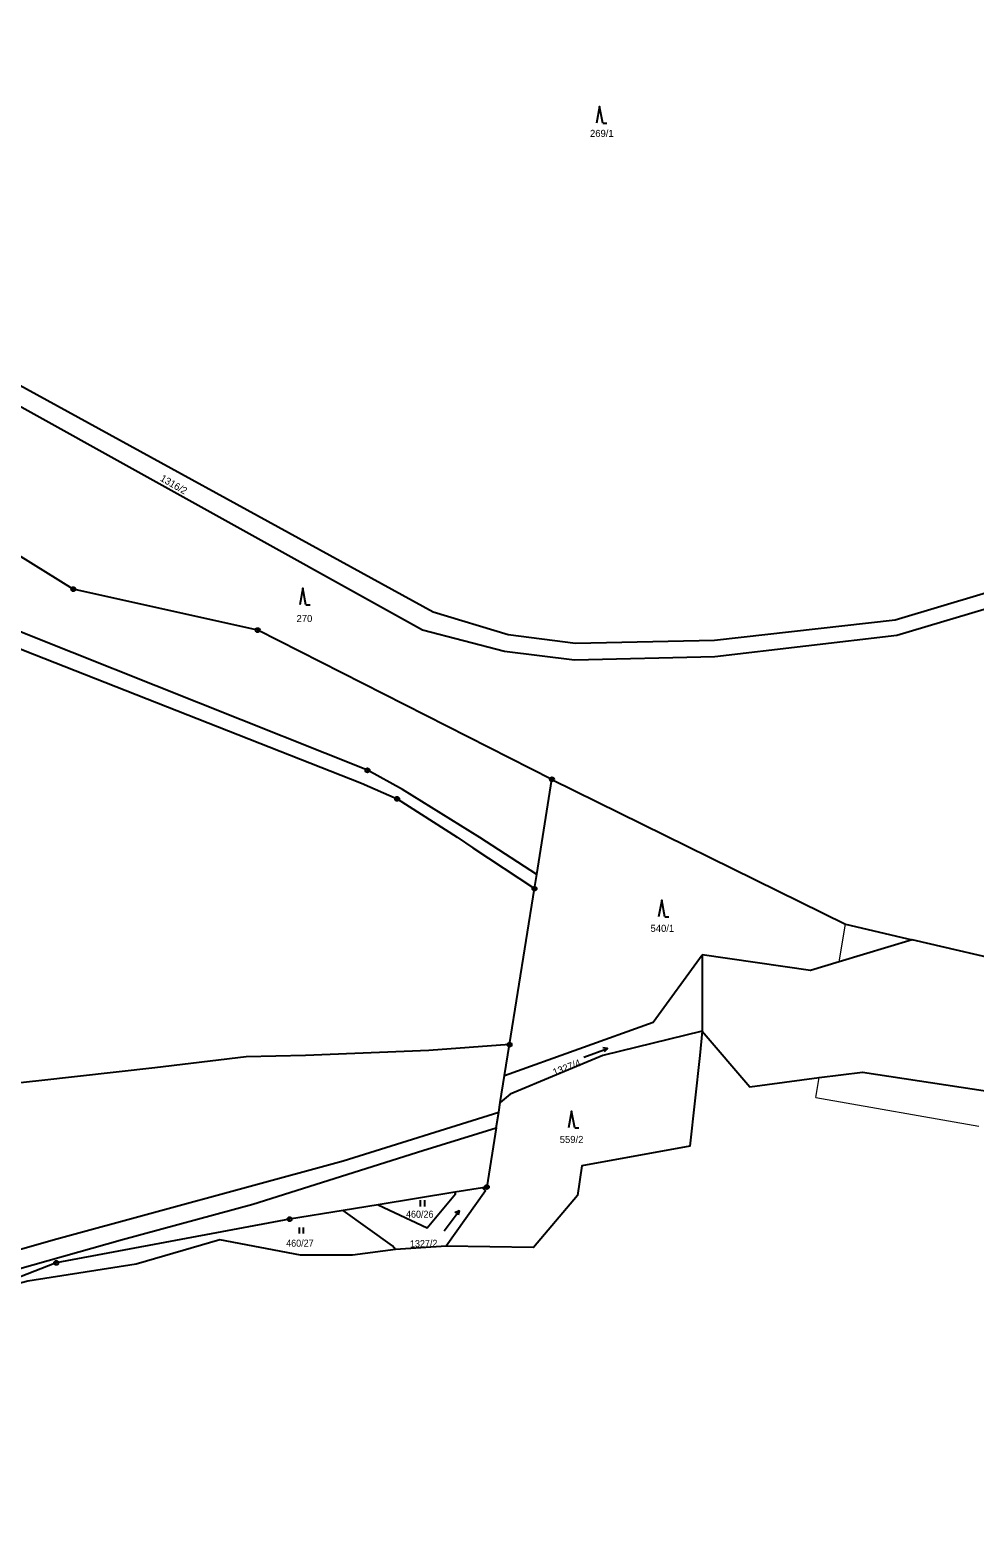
# Model space of a CAD drawing. Extents: x -872229 to -869198, y -1075981 to -1074329.
# Drawn here: x -869771.9 to -869544.8, y -1075316.1 to -1074953.6 of the extents above; entities that cross this region are included whole.
import ezdxf

# ---------------------------------------------------------------- set-up
doc = ezdxf.new("R2010")
doc.units = 0
doc.header["$LTSCALE"] = 0.68
for name, color, linetype, lineweight in [('1', 7, 'Continuous', 25), ('3', 7, 'Continuous', 25), ('4', 7, 'Continuous', 13), ('8', 7, 'Continuous', 25)]:
    doc.layers.add(name, color=color, linetype=linetype, lineweight=lineweight)
doc.layers.add('2', color=7, linetype='Continuous')

msp = doc.modelspace()

# ---------------------------------------------------------------- linework, layer by layer
at = {"layer": '1'}
for p, q in [((-869650.14, -1075156.59), (-869646.48, -1075133.71)), ((-869650.68, -1075159.97), (-869650.14, -1075156.59)), ((-869656.67, -1075197.48), (-869650.68, -1075159.97)), ((-869610.34, -1075175.92), (-869610.41, -1075194.26)), ((-869659.87, -1075217.53), (-869659.27, -1075213.75)), ((-869659.27, -1075213.75), (-869658.9, -1075211.43)), ((-869663.18, -1075231.88), (-869669.81, -1075232.97)), ((-869669.81, -1075232.97), (-869688.29, -1075235.98)), ((-869688.29, -1075235.98), (-869696.7, -1075237.35))]:
    msp.add_line(p, q, dxfattribs=at)
for points in [[(-869650.14, -1075156.59), (-869663.85, -1075147.72), (-869682.43, -1075136.12), (-869690.84, -1075131.53), (-869772.1, -1075099.13), (-869844.86, -1075069.32), (-869848.3, -1075067.94), (-869907.96, -1075043.15), (-869940.96, -1075028.98), (-869973.59, -1075015.13), (-869995.78, -1075005.14), (-870001.42, -1074998.91), (-870003.58, -1074990.56), (-870002.58, -1074982.27), (-870000.39, -1074972.48), (-869996.55, -1074953.58)], [(-869646.48, -1075133.71), (-869717.21, -1075097.82), (-869761.54, -1075087.98), (-869810.64, -1075057.49), (-869851.57, -1075052.75), (-869911.59, -1075031.3), (-869976.94, -1074996.08), (-869983.15, -1074985.9), (-869984.78, -1074967.82), (-869973.47, -1074958.19)], [(-869479.66, -1075070.06), (-869480.79, -1075070.33), (-869510.31, -1075083.29), (-869563.58, -1075099.14), (-869607.33, -1075104.27), (-869641.09, -1075105.05), (-869657.9, -1075102.95), (-869677.61, -1075097.87), (-869787.66, -1075036.73), (-869804.59, -1075028.78), (-869863.04, -1075007.07), (-869931.86, -1074972.77), (-869958.29, -1074958.82), (-869973.47, -1074958.19)], [(-869929.31, -1074968.38), (-869861.33, -1075003.43), (-869802.73, -1075024.51), (-869785.27, -1075033.02), (-869675.06, -1075093.42), (-869657.01, -1075098.88), (-869640.84, -1075100.95), (-869607.45, -1075100.23), (-869563.99, -1075095.38), (-869511.48, -1075079.68), (-869481.91, -1075066.7), (-869467.98, -1075063.1), (-869463.59, -1075063.5)], [(-870007.09, -1074982.34), (-870007.65, -1074991.46), (-870005.25, -1074999.97), (-870000.07, -1075005.82), (-869979.18, -1075015.56), (-869947.14, -1075029.34), (-869914.15, -1075043.78), (-869849.68, -1075071.21), (-869846.22, -1075072.58), (-869773.51, -1075102.64), (-869692.27, -1075134.64), (-869683.71, -1075138.39), (-869669.29, -1075147.62), (-869665.53, -1075150.2), (-869650.68, -1075159.97)], [(-869646.48, -1075133.71), (-869575.93, -1075168.51), (-869559.89, -1075172.26)], [(-869460.16, -1075167.77), (-869533.72, -1075178.38), (-869559.89, -1075172.26), (-869577.48, -1075177.56)], [(-869657.86, -1075204.9), (-869622.14, -1075192.1), (-869610.34, -1075175.92)], [(-869577.48, -1075177.56), (-869584.37, -1075179.64), (-869610.34, -1075175.92)], [(-869656.67, -1075197.48), (-869676.11, -1075198.92), (-869705.7, -1075200.11), (-869719.96, -1075200.44), (-869741.96, -1075203.08), (-869769.79, -1075206.17), (-869793.73, -1075208.74), (-869802.97, -1075209.8), (-869816.06, -1075208.55), (-869855.81, -1075204.07), (-869887.65, -1075202.22), (-869902.63, -1075201.56), (-869926.76, -1075200.04), (-869936.33, -1075199.65), (-869949.18, -1075200.24), (-869974.1, -1075201.42), (-869979.65, -1075201.82), (-869989.18, -1075200.96), (-870032.43, -1075196.35), (-870040.36, -1075195.42)], [(-869610.41, -1075194.26), (-869610.95, -1075200.13), (-869613.36, -1075221.91), (-869639.34, -1075226.59), (-869640.32, -1075233.75), (-869650.96, -1075246.23), (-869671.93, -1075245.96), (-869684.1, -1075246.72)], [(-869610.41, -1075194.26), (-869634.23, -1075200.13), (-869656.49, -1075209.41), (-869658.9, -1075211.43)], [(-869610.41, -1075194.26), (-869598.91, -1075207.6), (-869582.25, -1075205.43), (-869571.84, -1075204.08), (-869531.81, -1075210.17)], [(-869658.9, -1075211.43), (-869657.86, -1075204.9), (-869656.67, -1075197.48)], [(-870385.12, -1075316.07), (-870355.23, -1075301.89), (-870314.21, -1075282.93), (-870280.58, -1075266.36), (-870265.86, -1075261.9), (-870249.15, -1075258.69), (-870230, -1075254.57), (-870219.5, -1075254.87), (-870207.6, -1075253.65), (-870190, -1075251.81), (-870178.96, -1075255.5), (-870167.23, -1075255.17), (-870141.46, -1075254.46), (-870092.41, -1075254.3), (-870019.81, -1075254.06), (-869952.16, -1075254.08), (-869902.23, -1075254.21), (-869809.43, -1075253.56), (-869784.98, -1075249.67), (-869765.49, -1075244.15), (-869696.7, -1075225.43), (-869659.27, -1075213.75)], [(-870086.74, -1075257.68), (-870033.35, -1075257.7), (-869997.08, -1075257.38), (-869953.96, -1075258.61), (-869925.38, -1075258.43), (-869886.31, -1075258.63), (-869811.48, -1075257.76), (-869785.54, -1075254.45), (-869749.68, -1075244.36), (-869718.38, -1075235.81), (-869677.56, -1075222.96), (-869659.87, -1075217.53)], [(-869659.87, -1075217.53), (-869662.14, -1075231.71), (-869663.18, -1075231.88)], [(-869663.18, -1075231.88), (-869662.47, -1075232.67), (-869671.93, -1075245.96)], [(-869688.29, -1075235.98), (-869676.45, -1075241.57), (-869669.7, -1075233.33), (-869669.81, -1075232.97)], [(-869709.56, -1075239.45), (-869765.65, -1075249.96), (-869788.46, -1075258.83)], [(-869684.1, -1075246.72), (-869684.85, -1075245.87), (-869696.7, -1075237.35), (-869709.56, -1075239.45)], [(-869684.1, -1075246.72), (-869694.41, -1075248.14), (-869706.94, -1075248.13), (-869726.28, -1075244.45), (-869746.39, -1075250.29), (-869772.5, -1075254.32), (-869779.17, -1075256.14), (-869786.75, -1075258.83)]]:
    msp.add_lwpolyline(points, dxfattribs=at)
at = {"layer": '3'}
for p, q in [((-869634.27, -1074975.95), (-869633.274, -1074975.95)), ((-869705.61, -1075091.77), (-869704.614, -1075091.77)), ((-869619.35, -1075166.75), (-869618.354, -1075166.75)), ((-869633.152, -1075198.426), (-869633.899, -1075199.232)), ((-869641.01, -1075217.5), (-869640.014, -1075217.5)), ((-869678.051, -1075236.4), (-869678.051, -1075234.9)), ((-869677.05, -1075236.4), (-869677.05, -1075234.9)), ((-869668.807, -1075237.446), (-869668.995, -1075238.528)), ((-869707.201, -1075242.92), (-869707.201, -1075241.42)), ((-869706.2, -1075242.92), (-869706.2, -1075241.42))]:
    msp.add_line(p, q, dxfattribs=at)
for points in [[(-869634.27, -1074975.95), (-869635.02, -1074971.95), (-869635.77, -1074975.95)], [(-869705.61, -1075091.77), (-869706.36, -1075087.77), (-869707.11, -1075091.77)], [(-869619.35, -1075166.75), (-869620.1, -1075162.75), (-869620.85, -1075166.75)], [(-869638.79, -1075200.478), (-869633.152, -1075198.426), (-869634.242, -1075198.289)], [(-869641.01, -1075217.5), (-869641.76, -1075213.5), (-869642.51, -1075217.5)], [(-869672.418, -1075242.237), (-869668.807, -1075237.446), (-869669.796, -1075237.924)]]:
    msp.add_lwpolyline(points, dxfattribs=at)
at = {"layer": '4'}
for p, q in [((-869577.48, -1075177.56), (-869575.93, -1075168.51)), ((-869583.06, -1075210.18), (-869582.25, -1075205.43)), ((-869583.06, -1075210.18), (-869543.86, -1075217.07))]:
    msp.add_line(p, q, dxfattribs=at)
at = {"layer": '8'}
for centre, radius in [((-869761.54, -1075087.9799), 0.5), ((-869761.54, -1075087.9799), 0.0303), ((-869717.21, -1075097.8199), 0.5), ((-869717.21, -1075097.8199), 0.0303), ((-869690.84, -1075131.5299), 0.5), ((-869690.84, -1075131.5299), 0.0303), ((-869646.48, -1075133.7099), 0.5), ((-869646.48, -1075133.7099), 0.0303), ((-869683.71, -1075138.3899), 0.5), ((-869683.71, -1075138.3899), 0.0303), ((-869650.68, -1075159.9699), 0.5), ((-869650.68, -1075159.9699), 0.0303), ((-869656.67, -1075197.4799), 0.5), ((-869656.67, -1075197.4799), 0.0303), ((-869662.14, -1075231.7099), 0.5), ((-869662.14, -1075231.7099), 0.0303), ((-869709.56, -1075239.4499), 0.5), ((-869709.56, -1075239.4499), 0.0303), ((-869765.65, -1075249.9599), 0.5), ((-869765.65, -1075249.9599), 0.0303)]:
    msp.add_circle(centre, radius, dxfattribs=at)

# ---------------------------------------------------------------- texts
at = {"layer": '2'}
for s, p in [('269/1', (-869637.34, -1074979.25)), ('270', (-869707.88, -1075095.9)), ('540/1', (-869622.79, -1075170.37)), ('559/2', (-869644.61, -1075221.13))]:
    msp.add_text(s, height=1.7, dxfattribs=at).set_placement(p)
for s, rotation, p in [('1316/2', 330, (-869740.825, -1075061.806)), ('1327/4', 21, (-869645.895, -1075205.013))]:
    msp.add_text(s, height=1.7, rotation=rotation, dxfattribs=at).set_placement(p)
at = {"layer": '2', "width": 0.95}
for s, p in [('460/26', (-869681.57, -1075239.11)), ('460/27', (-869710.37, -1075246.07))]:
    msp.add_text(s, height=1.7, dxfattribs=at).set_placement(p)
msp.add_text('1327/2', height=1.7, rotation=1, dxfattribs=at).set_placement((-869680.605, -1075246.219))

doc.saveas('drawing.dxf')
